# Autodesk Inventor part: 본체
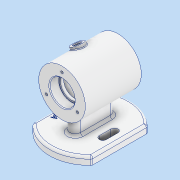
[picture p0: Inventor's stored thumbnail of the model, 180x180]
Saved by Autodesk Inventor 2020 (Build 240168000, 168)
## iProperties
Created: 2022-02
Part Number: 본체
Material: 알루미늄 6061
Document SubType Name: Modeling
Designer: 605-4
Density: 2.7 g/cm^3
Appearance: 알루미늄 - 평지
Mass: 494.89 g
Surface Area: 490.665 cm^2
Volume: 183.293 cm^3
Author: 605-4
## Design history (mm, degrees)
sketch "스케치1"
  geometry: C1 r 30 at (0, 0); 1 further point
  constraints: 1 centre point, 1 coincident
  dimensions: "d0" = 60 diameter of C1
extrude "돌출1" new body sketch "스케치1" stored distance "d1" = 72; taper "d2" = 0 deg
sketch "스케치2"
  geometry: L1 (-30, -36)-(30, -36) reference; L2 (30, 36)-(-30, 36) reference; L3 (0, 36)-(16, 36); L4 (16, 36)-(16, 24); L5 (16, 24)-(0, 24); L6 (0, 24)-(0, 36); L7 (0, 24)-(14, 24); L8 (14, 24)-(14, 20); L9 (14, 20)-(0, 20); L10 (0, 20)-(0, 24); L11 (0, 20)-(25, 20); L12 (25, 20)-(25, -20); L13 (25, -20)-(0, -20); L14 (0, -20)-(0, 20); L15 (0, -20)-(14, -20); L16 (14, -20)-(14, -24); L17 (14, -24)-(0, -24); L18 (0, -24)-(0, -20); L19 (-30, -36)-(30, -36) reference; L20 (0, -24)-(16, -24); L21 (16, -24)-(16, -36); L22 (16, -36)-(0, -36); L23 (0, -36)-(0, -24); L24 (-30, -36)-(-30, 36) reference; L25 (30, -36)-(30, 36) reference; 10 further points
  constraints: 40 end point, 10 parallel, 5 horizontal, 5 perpendicular, 3 midpoint, 1 horizontal alignment, 1 point on line
  dimensions: "d3" = 12 distance of L3.end L4.end; "d4" = 12 distance of L20.end L21.end; "d5" = 40 distance of L11.end L12.end; "d6" = 50 diameter of L12 L14; "d7" = 32 diameter of L21 L23; "d8" = 28 diameter of L16 L18; "d9" = 32 diameter of L4 L6; "d10" = 28 diameter of L8 L10
revolve "회전1" sketch "스케치2" stored, may be unused: angle "d11" = 90 deg
node "작업 평면1"
sketch "스케치3"
  geometry: L1 (0, 52)-(0, -52); L2 (38, 35.496)-(38, -35.496); L3 (-38, 35.496)-(-38, -35.496); A1 r 52 centre (0, 0) between (38, 35.496) and (-38, 35.496); A2 r 52 centre (0, 0) between (-38, -35.496) and (38, -35.496); 1 further point
  constraints: 6 end point, 6 point on circle, 3 parallel, 2 centre point, 1 coincident, 1 concentric, 1 vertical
  dimensions: "d14" = 38 distance between parallel lines of L1 L2; "d15" = 38 distance between parallel lines of L1 L3; "d16" = 52 radius of A2
extrude "돌출2" join sketch "스케치3" distance "d17" = 10; taper "d18" = 0 deg
sketch "스케치4" dims "d19" = 46
  geometry: 4 further points
  constraints: 1 coincident, 1 vertical alignment, 2 other
hole "구멍1" sketch "스케치4" at (0, 23), (92.902, 40.573) diameter "d20" = 3.242; stored, may be unused: countersink angle "d24" = 90 deg, drill point angle "d26" = 118 deg; dims "d21" = 8, "d22" = 4, "d23" = 2, "d25" = 10
sketch "스케치5"
  geometry: L1 (0, 19)-(0, -19); L2 (-7, 19)-(-7, -19); L3 (7, -19)-(7, 19); A1 r 7 centre (0, 19) between (7, 19) and (-7, 19); A2 r 7 centre (0, -19) between (-7, -19) and (7, -19); 2 further points
  constraints: 8 end point, 4 point on circle, 4 tangent, 2 centre point, 1 coincident, 1 midpoint, 1 parallel, 1 vertical
  dimensions: "d30" = 14 diameter of A2; "d31" = 38 distance of L1.start L1.end
extrude "돌출3" join sketch "스케치5" stored distance "d32" = 10; taper "d33" = 0 deg
sketch "스케치6"
  geometry: L1 (-24, 7.5)-(-24, -7.5); L2 (-28.5, 7.5)-(-28.5, -7.5); L3 (-19.5, -7.5)-(-19.5, 7.5); A1 r 4.5 centre (-24, 7.5) between (-19.5, 7.5) and (-28.5, 7.5); A2 r 4.5 centre (-24, -7.5) between (-28.5, -7.5) and (-19.5, -7.5); 2 further points
  constraints: 8 end point, 4 point on circle, 4 tangent, 2 centre point, 1 horizontal alignment, 1 midpoint, 1 parallel, 1 vertical
  dimensions: "d34" = 9 diameter of A2; "d35" = 15 distance of L1.end L1.start; "d36" = 24 distance from line of L1 point (0, 0)
extrude "돌출4" cut sketch "스케치6" distance "d37" = 10; taper "d38" = 0 deg
sketch "스케치7"
  geometry: L1 (0, 0)-(0, 30); L2 (0, 0)-(-16.5, 28.579); L3 (0, 0)-(-19.919, -11.5); C1 r 14 at (0, 0) reference; C2 r 1.621 at (-19.919, -11.5) reference; C3 r 1.621 at (-19.919, -11.5) reference; 1 further point
  constraints: 6 end point, 1 vertical, 1 vertical alignment, 1 other
  dimensions: "d39" = 30 deg angle of L2 L1; "d64" = 33 distance from line of L2.end L3
node "작업 평면2"
sketch "스케치8"
  geometry: C1 r 8 at (0, 0); 2 further points
  constraints: 2 coincident, 1 centre point
  dimensions: "d41" = 16 diameter of C1
extrude "돌출5" join sketch "스케치8" stored distance "d42" = 10; taper "d43" = 0 deg
sketch "스케치9"
  geometry: 1 further point
hole "구멍2" sketch "스케치9" at (0, 0) diameter "d44" = 8; stored, may be unused: countersink angle "d48" = 90 deg, drill point angle "d50" = 0 deg; dims "d45" = 8, "d46" = 4, "d47" = 2, "d49" = 10
chamfer "모따기1" distance "d51" = 1; stored, may be unused: second distance "d52" = 2, angle "d53" = 45 deg
fillet "모깎기1" dims "d54" = 0.3
fillet "모깎기2" dims "d55" = 3
fillet "모깎기3" dims "d56" = 1
fillet "모깎기4" dims "d57" = 1
fillet "모깎기5" dims "d58" = 3
fillet "모깎기6" dims "d59" = 3
fillet "모깎기7" dims "d60" = 3
sketch "스케치10"
  geometry: C1 r 36.5 at (0, 0); 1 further point
  constraints: 1 centre point, 1 coincident, 1 other
  dimensions: "d61" = 73 diameter of C1
feature "엠보싱1" sketch "스케치10" dims "d3" = 12, "d4" = 12, "d5" = 40, "d6" = 50, "d7" = 32, "d8" = 28, "d9" = 32, "d10" = 28, "d62" = 0.5, "d63" = 0
node "솔리드1"
pattern_circular "원형 패턴1" dims angle "d28" = 360 deg
mirror "미러1"
mirror "미러2"
node "투영된 루프1"
feature "A9D066F2-1C7D-4E18-AEED-F7BC21143FA4" dims "d44" = 8, "d45" = 8, "d46" = 4, "d47" = 2, "d48" = 90 deg, "d49" = 10, "d50" = 0
other parameters: "d12" = -62, "d13" = 104
